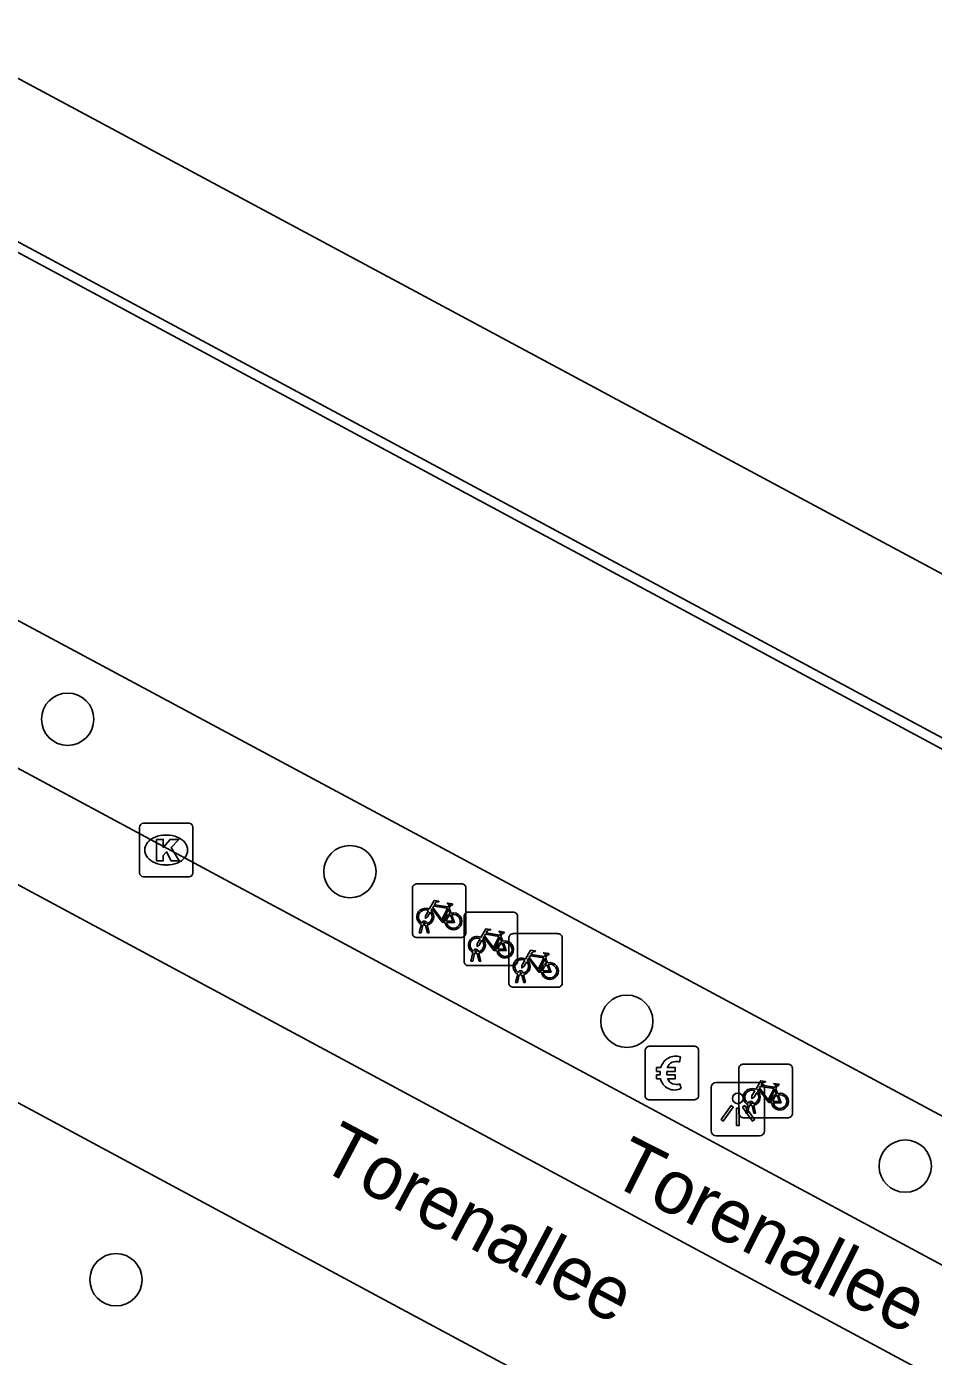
# Model space of a CAD drawing. Extents: x 159489 to 160304, y 383826 to 384530.
# Drawn here: x 159929.09 to 159946.05, y 384136.73 to 384161.6 of the extents above; entities that cross this region are included whole.
import ezdxf

# ---------------------------------------------------------------- set-up
doc = ezdxf.new("R2010")
doc.units = 0
for name, color, linetype in [('IMGEO_Betaalautomaat', 7, 'Continuous'), ('IMGEO_Boom', 7, 'Continuous'), ('IMGEO_Fietsenrek', 7, 'Continuous'), ('IMGEO_Kolk', 7, 'Continuous'), ('IMGEO_Lichtpunt', 7, 'Continuous'), ('IMGEO_Lijnafwatering', 7, 'Continuous'), ('IMGEO_Openbare_ruimte_label', 7, 'Continuous'), ('IMGEO_Pand', 7, 'Continuous'), ('IMGEO_Rijbaan_lokaal_gesloten', 7, 'Continuous'), ('IMGEO_Voetpad_open', 7, 'Continuous')]:
    doc.layers.add(name, color=color, linetype=linetype)

msp = doc.modelspace()

# ---------------------------------------------------------------- linework, layer by layer
at = {"layer": 'IMGEO_Betaalautomaat'}
for p, q in [((159940.662, 384141.609), (159940.662, 384142.45)), ((159940.662, 384142.45), (159940.662, 384141.609)), ((159940.737, 384142.533), (159941.578, 384142.533)), ((159941.578, 384142.533), (159940.737, 384142.533)), ((159941.661, 384142.459), (159941.661, 384141.618)), ((159941.661, 384141.618), (159941.661, 384142.459)), ((159941.324, 384142.338), (159941.307, 384142.238)), ((159940.945, 384141.997), (159940.945, 384142.065)), ((159941.066, 384142.065), (159941.066, 384141.997)), ((159941.311, 384141.832), (159941.333, 384141.745)), ((159941.587, 384141.534), (159940.746, 384141.534)), ((159940.746, 384141.534), (159941.587, 384141.534))]:
    msp.add_line(p, q, dxfattribs=at)
for points in [[(159940.945, 384142.065), (159940.876, 384142.065), (159940.876, 384142.134), (159940.955, 384142.134)], [(159940.95, 384141.928), (159940.876, 384141.928), (159940.876, 384141.997), (159940.945, 384141.997)], [(159941.077, 384142.134), (159941.224, 384142.134), (159941.224, 384142.065), (159941.066, 384142.065)], [(159941.066, 384141.997), (159941.224, 384141.997), (159941.224, 384141.928), (159941.08, 384141.928)]]:
    msp.add_lwpolyline(points, dxfattribs=at)
for centre, radius, start, end in [((159940.74, 384142.456), 0.0779, 92.4484, 184.2845), ((159940.74, 384142.456), 0.0779, 92.4484, 184.2845), ((159941.584, 384142.456), 0.0779, 2.4484, 94.2845), ((159941.584, 384142.456), 0.0779, 2.4484, 94.2845), ((159941.238, 384142.058), 0.293, 73.014, 165.0139), ((159941.244, 384142.071), 0.179, 69.3236, 159.5683), ((159941.211, 384141.983), 0.267, 191.8096, 297.0389), ((159941.244, 384141.998), 0.179, 202.7625, 291.8693), ((159940.74, 384141.612), 0.0779, 182.4484, 274.2845), ((159940.74, 384141.612), 0.0779, 182.4484, 274.2845), ((159941.584, 384141.612), 0.0779, 272.4484, 4.2845), ((159941.584, 384141.612), 0.0779, 272.4484, 4.2845)]:
    msp.add_arc(centre, radius, start, end, dxfattribs=at)
at = {"layer": 'IMGEO_Boom'}
for centre in [(159929.858, 384148.65), (159935.138, 384145.8), (159940.319, 384143.002), (159945.528, 384140.293), (159930.762, 384138.168)]:
    msp.add_circle(centre, 0.489, dxfattribs=at)
at = {"layer": 'IMGEO_Fietsenrek'}
for p, q in [((159936.308, 384144.645), (159936.308, 384145.486)), ((159936.308, 384145.486), (159936.308, 384144.645)), ((159936.383, 384145.57), (159937.224, 384145.57)), ((159937.224, 384145.57), (159936.383, 384145.57)), ((159937.308, 384145.495), (159937.308, 384144.654)), ((159937.308, 384144.654), (159937.308, 384145.495)), ((159936.995, 384145.119), (159937.031, 384145.024)), ((159937.275, 384144.118), (159937.275, 384144.959)), ((159937.275, 384144.959), (159937.275, 384144.118)), ((159937.35, 384145.043), (159938.191, 384145.043)), ((159938.191, 384145.043), (159937.35, 384145.043)), ((159938.275, 384144.968), (159938.275, 384144.127)), ((159938.275, 384144.127), (159938.275, 384144.968)), ((159936.435, 384144.654), (159936.474, 384144.814)), ((159936.469, 384144.654), (159936.435, 384144.654)), ((159936.504, 384144.802), (159936.469, 384144.654)), ((159936.546, 384144.826), (159936.545, 384144.83)), ((159936.587, 384144.654), (159936.553, 384144.796)), ((159936.577, 384144.837), (159936.578, 384144.83)), ((159936.585, 384144.8), (159936.62, 384144.654)), ((159936.62, 384144.654), (159936.587, 384144.654)), ((159938.187, 384144.64), (159939.028, 384144.64)), ((159939.028, 384144.64), (159938.187, 384144.64)), ((159937.233, 384144.57), (159936.392, 384144.57)), ((159936.392, 384144.57), (159937.233, 384144.57)), ((159937.962, 384144.592), (159937.998, 384144.497)), ((159938.112, 384143.715), (159938.112, 384144.556)), ((159938.112, 384144.556), (159938.112, 384143.715)), ((159939.112, 384144.565), (159939.112, 384143.724)), ((159939.112, 384143.724), (159939.112, 384144.565)), ((159937.402, 384144.127), (159937.441, 384144.287)), ((159937.471, 384144.275), (159937.436, 384144.127)), ((159937.513, 384144.299), (159937.512, 384144.303)), ((159937.554, 384144.127), (159937.52, 384144.269)), ((159937.544, 384144.31), (159937.545, 384144.303)), ((159937.552, 384144.273), (159937.587, 384144.127)), ((159938.799, 384144.189), (159938.835, 384144.094)), ((159938.2, 384144.043), (159937.359, 384144.043)), ((159937.359, 384144.043), (159938.2, 384144.043)), ((159937.436, 384144.127), (159937.402, 384144.127)), ((159937.587, 384144.127), (159937.554, 384144.127)), ((159938.35, 384143.896), (159938.349, 384143.9)), ((159938.381, 384143.907), (159938.382, 384143.9)), ((159939.037, 384143.64), (159938.196, 384143.64)), ((159938.196, 384143.64), (159939.037, 384143.64)), ((159938.239, 384143.724), (159938.278, 384143.884)), ((159938.273, 384143.724), (159938.239, 384143.724)), ((159938.308, 384143.872), (159938.273, 384143.724)), ((159938.391, 384143.724), (159938.357, 384143.866)), ((159938.389, 384143.87), (159938.424, 384143.724)), ((159938.424, 384143.724), (159938.391, 384143.724)), ((159942.492, 384142.198), (159943.333, 384142.198)), ((159943.333, 384142.198), (159942.492, 384142.198)), ((159942.417, 384141.273), (159942.417, 384142.114)), ((159942.417, 384142.114), (159942.417, 384141.273)), ((159943.417, 384142.123), (159943.417, 384141.282)), ((159943.417, 384141.282), (159943.417, 384142.123)), ((159943.104, 384141.747), (159943.14, 384141.652)), ((159942.544, 384141.282), (159942.583, 384141.442)), ((159942.613, 384141.43), (159942.578, 384141.282)), ((159942.655, 384141.454), (159942.654, 384141.458)), ((159942.696, 384141.282), (159942.662, 384141.424)), ((159942.686, 384141.465), (159942.687, 384141.458)), ((159942.694, 384141.428), (159942.729, 384141.282)), ((159943.342, 384141.198), (159942.501, 384141.198)), ((159942.501, 384141.198), (159943.342, 384141.198)), ((159942.578, 384141.282), (159942.544, 384141.282)), ((159942.729, 384141.282), (159942.696, 384141.282))]:
    msp.add_line(p, q, dxfattribs=at)
for points in [[(159936.621, 384145.096), (159936.716, 384145.26), (159936.802, 384145.246), (159936.804, 384145.237), (159936.748, 384145.226), (159936.721, 384145.181), (159936.977, 384145.14)], [(159936.964, 384145.115), (159936.707, 384145.156), (159936.69, 384145.127), (159936.857, 384144.907), (159936.964, 384145.115)], [(159936.977, 384145.14), (159937.002, 384145.189), (159936.996, 384145.193), (159936.973, 384145.197), (159936.961, 384145.204), (159936.96, 384145.207), (159936.962, 384145.212), (159937.057, 384145.197), (159937.059, 384145.187), (159937.049, 384145.174), (159937.037, 384145.168), (159937.023, 384145.174), (159936.995, 384145.119)], [(159936.642, 384145.044), (159936.59, 384144.954), (159936.55, 384144.929), (159936.551, 384144.976), (159936.606, 384145.07)], [(159936.917, 384144.852), (159936.867, 384144.852), (159936.676, 384145.103), (159936.657, 384145.071)], [(159937.012, 384145.017), (159936.982, 384145.094), (159936.873, 384144.876), (159936.916, 384144.876)], [(159936.946, 384144.876), (159937.066, 384144.875), (159937.022, 384144.989)], [(159937.042, 384144.996), (159937.097, 384144.851), (159936.947, 384144.851)], [(159937.588, 384144.569), (159937.683, 384144.733), (159937.769, 384144.719), (159937.771, 384144.71), (159937.715, 384144.699), (159937.688, 384144.654), (159937.944, 384144.613)], [(159937.944, 384144.613), (159937.969, 384144.662), (159937.963, 384144.666), (159937.94, 384144.67), (159937.928, 384144.677), (159937.927, 384144.68), (159937.929, 384144.685), (159938.024, 384144.67), (159938.026, 384144.66), (159938.016, 384144.647), (159938.004, 384144.641), (159937.99, 384144.647), (159937.962, 384144.592)], [(159937.609, 384144.517), (159937.557, 384144.427), (159937.517, 384144.402), (159937.518, 384144.449), (159937.573, 384144.543)], [(159937.884, 384144.325), (159937.834, 384144.325), (159937.643, 384144.576), (159937.624, 384144.544)], [(159937.931, 384144.588), (159937.674, 384144.629), (159937.657, 384144.6), (159937.824, 384144.38), (159937.931, 384144.588)], [(159937.979, 384144.49), (159937.949, 384144.567), (159937.84, 384144.349), (159937.883, 384144.349)], [(159937.913, 384144.349), (159938.033, 384144.348), (159937.989, 384144.462)], [(159938.009, 384144.469), (159938.064, 384144.324), (159937.914, 384144.324)], [(159938.446, 384144.114), (159938.394, 384144.024), (159938.354, 384143.999), (159938.355, 384144.046), (159938.41, 384144.14)], [(159938.425, 384144.166), (159938.52, 384144.33), (159938.606, 384144.316), (159938.608, 384144.307), (159938.552, 384144.296), (159938.525, 384144.251), (159938.781, 384144.21)], [(159938.721, 384143.922), (159938.671, 384143.922), (159938.48, 384144.173), (159938.461, 384144.141)], [(159938.768, 384144.185), (159938.511, 384144.226), (159938.494, 384144.197), (159938.661, 384143.977), (159938.768, 384144.185)], [(159938.816, 384144.087), (159938.786, 384144.164), (159938.677, 384143.946), (159938.72, 384143.946)], [(159938.781, 384144.21), (159938.806, 384144.259), (159938.8, 384144.263), (159938.777, 384144.267), (159938.765, 384144.274), (159938.764, 384144.277), (159938.766, 384144.282), (159938.861, 384144.267), (159938.863, 384144.257), (159938.853, 384144.244), (159938.841, 384144.238), (159938.827, 384144.244), (159938.799, 384144.189)], [(159938.75, 384143.946), (159938.87, 384143.945), (159938.826, 384144.059)], [(159938.846, 384144.066), (159938.901, 384143.921), (159938.751, 384143.921)], [(159942.751, 384141.672), (159942.699, 384141.582), (159942.659, 384141.557), (159942.66, 384141.604), (159942.715, 384141.698)], [(159942.73, 384141.724), (159942.825, 384141.888), (159942.911, 384141.874), (159942.913, 384141.865), (159942.857, 384141.854), (159942.83, 384141.809), (159943.086, 384141.768)], [(159943.026, 384141.48), (159942.976, 384141.48), (159942.785, 384141.731), (159942.766, 384141.699)], [(159943.073, 384141.743), (159942.816, 384141.784), (159942.799, 384141.755), (159942.966, 384141.535), (159943.073, 384141.743)], [(159943.121, 384141.645), (159943.091, 384141.722), (159942.982, 384141.504), (159943.025, 384141.504)], [(159943.086, 384141.768), (159943.111, 384141.817), (159943.105, 384141.821), (159943.082, 384141.825), (159943.07, 384141.832), (159943.069, 384141.835), (159943.071, 384141.84), (159943.166, 384141.825), (159943.168, 384141.815), (159943.158, 384141.802), (159943.146, 384141.796), (159943.132, 384141.802), (159943.104, 384141.747)], [(159943.055, 384141.504), (159943.175, 384141.503), (159943.131, 384141.617)], [(159943.151, 384141.624), (159943.206, 384141.479), (159943.056, 384141.479)]]:
    msp.add_lwpolyline(points, dxfattribs=at)
for centre, radius, start, end in [((159936.386, 384145.492), 0.0779, 92.4484, 184.2845), ((159936.386, 384145.492), 0.0779, 92.4484, 184.2845), ((159937.23, 384145.492), 0.0779, 2.4484, 94.2845), ((159937.23, 384145.492), 0.0779, 2.4484, 94.2845), ((159936.548, 384144.955), 0.159, 62.6766, 242.1369), ((159936.548, 384144.955), 0.129, 63.3192, 238.903), ((159936.548, 384144.955), 0.129, 283.6043, 43.4302), ((159936.548, 384144.955), 0.159, 283.5766, 46.6042), ((159937.075, 384144.871), 0.159, 113.3408, 178.3217), ((159937.075, 384144.871), 0.159, 187.0065, 105.7708), ((159937.075, 384144.871), 0.129, 113.923, 177.9556), ((159937.075, 384144.871), 0.129, 188.6715, 104.5883), ((159937.353, 384144.965), 0.0779, 92.4484, 184.2845), ((159937.353, 384144.965), 0.0779, 92.4484, 184.2845), ((159938.197, 384144.965), 0.0779, 2.4484, 94.2845), ((159938.197, 384144.965), 0.0779, 2.4484, 94.2845), ((159936.386, 384144.648), 0.0779, 182.4484, 274.2845), ((159936.386, 384144.648), 0.0779, 182.4484, 274.2845), ((159936.528, 384144.826), 0.0499, 12.8025, 158.6934), ((159936.548, 384144.955), 0.159, 253.9967, 271.7867), ((159936.528, 384144.826), 0.0174, 12.8025, 163.4502), ((159936.548, 384144.955), 0.129, 253.415, 269.0204), ((159937.23, 384144.648), 0.0779, 272.4484, 4.2845), ((159937.23, 384144.648), 0.0779, 272.4484, 4.2845), ((159938.19, 384144.562), 0.0779, 92.4484, 184.2845), ((159938.19, 384144.562), 0.0779, 92.4484, 184.2845), ((159939.034, 384144.562), 0.0779, 2.4484, 94.2845), ((159939.034, 384144.562), 0.0779, 2.4484, 94.2845), ((159937.515, 384144.428), 0.159, 62.6766, 242.1369), ((159937.515, 384144.428), 0.129, 63.3192, 238.903), ((159937.515, 384144.428), 0.129, 283.6043, 43.4302), ((159937.515, 384144.428), 0.159, 283.5766, 46.6042), ((159938.042, 384144.344), 0.159, 113.3408, 178.3217), ((159938.042, 384144.344), 0.159, 187.0065, 105.7708), ((159938.042, 384144.344), 0.129, 113.923, 177.9556), ((159938.042, 384144.344), 0.129, 188.6715, 104.5883), ((159937.495, 384144.299), 0.0499, 12.8025, 158.6934), ((159937.515, 384144.428), 0.159, 253.9967, 271.7867), ((159937.495, 384144.299), 0.0174, 12.8025, 163.4502), ((159937.515, 384144.428), 0.129, 253.415, 269.0204), ((159938.352, 384144.025), 0.159, 62.6766, 242.1369), ((159938.352, 384144.025), 0.129, 63.3192, 238.903), ((159938.352, 384144.025), 0.159, 283.5766, 46.6042), ((159937.353, 384144.121), 0.0779, 182.4484, 274.2845), ((159937.353, 384144.121), 0.0779, 182.4484, 274.2845), ((159938.197, 384144.121), 0.0779, 272.4484, 4.2845), ((159938.197, 384144.121), 0.0779, 272.4484, 4.2845), ((159938.332, 384143.896), 0.0499, 12.8025, 158.6934), ((159938.332, 384143.896), 0.0174, 12.8025, 163.4502), ((159938.352, 384144.025), 0.129, 253.415, 269.0204), ((159938.352, 384144.025), 0.129, 283.6043, 43.4302), ((159938.879, 384143.941), 0.159, 113.3408, 178.3217), ((159938.879, 384143.941), 0.159, 187.0065, 105.7708), ((159938.879, 384143.941), 0.129, 113.923, 177.9556), ((159938.879, 384143.941), 0.129, 188.6715, 104.5883), ((159938.19, 384143.718), 0.0779, 182.4484, 274.2845), ((159938.19, 384143.718), 0.0779, 182.4484, 274.2845), ((159938.352, 384144.025), 0.159, 253.9967, 271.7867), ((159939.034, 384143.718), 0.0779, 272.4484, 4.2845), ((159939.034, 384143.718), 0.0779, 272.4484, 4.2845), ((159942.495, 384142.12), 0.0779, 92.4484, 184.2845), ((159942.495, 384142.12), 0.0779, 92.4484, 184.2845), ((159943.339, 384142.12), 0.0779, 2.4484, 94.2845), ((159943.339, 384142.12), 0.0779, 2.4484, 94.2845), ((159942.657, 384141.583), 0.159, 62.6766, 242.1369), ((159942.657, 384141.583), 0.129, 63.3192, 238.903), ((159942.657, 384141.583), 0.129, 283.6043, 43.4302), ((159942.657, 384141.583), 0.159, 283.5766, 46.6042), ((159943.184, 384141.499), 0.159, 187.0065, 105.7708), ((159942.637, 384141.454), 0.0499, 12.8025, 158.6934), ((159942.657, 384141.583), 0.159, 253.9967, 271.7867), ((159942.637, 384141.454), 0.0174, 12.8025, 163.4502), ((159942.657, 384141.583), 0.129, 253.415, 269.0204), ((159943.184, 384141.499), 0.159, 113.3408, 178.3217), ((159943.184, 384141.499), 0.129, 113.923, 177.9556), ((159943.184, 384141.499), 0.129, 188.6715, 104.5883), ((159942.495, 384141.276), 0.0779, 182.4484, 274.2845), ((159942.495, 384141.276), 0.0779, 182.4484, 274.2845), ((159943.339, 384141.276), 0.0779, 272.4484, 4.2845), ((159943.339, 384141.276), 0.0779, 272.4484, 4.2845)]:
    msp.add_arc(centre, radius, start, end, dxfattribs=at)
at = {"layer": 'IMGEO_Kolk'}
for p, q in [((159931.201, 384145.778), (159931.201, 384146.63)), ((159931.276, 384146.704), (159932.128, 384146.704)), ((159932.202, 384146.63), (159932.202, 384145.778)), ((159931.689, 384146.484), (159931.714, 384146.484)), ((159931.712, 384145.924), (159931.687, 384145.924)), ((159932.128, 384145.704), (159931.276, 384145.704))]:
    msp.add_line(p, q, dxfattribs=at)
for points in [[(159931.201, 384145.778), (159931.201, 384146.63)], [(159931.276, 384146.704), (159932.128, 384146.704)], [(159932.202, 384146.63), (159932.202, 384145.778)], [(159931.522, 384146.404), (159931.645, 384146.404), (159931.645, 384146.253), (159931.775, 384146.404), (159931.939, 384146.404), (159931.793, 384146.253), (159931.946, 384146.004), (159931.794, 384146.004), (159931.709, 384146.168), (159931.645, 384146.101), (159931.645, 384146.004), (159931.522, 384146.004), (159931.522, 384146.404)], [(159932.128, 384145.704), (159931.276, 384145.704)]]:
    msp.add_lwpolyline(points, dxfattribs=at)
for centre, start, end in [((159931.278, 384146.628), 91.552, 178.448), ((159931.278, 384146.628), 91.552, 178.448), ((159932.126, 384146.628), 1.552, 88.448), ((159932.126, 384146.628), 1.552, 88.448), ((159931.278, 384145.78), 181.552, 268.448), ((159931.278, 384145.78), 181.552, 268.448), ((159932.126, 384145.78), 271.552, 358.448), ((159932.126, 384145.78), 271.552, 358.448)]:
    msp.add_arc(centre, 0.0765, start, end, dxfattribs=at)
for centre, major_axis, ratio, start_param, end_param in [((159931.688, 384146.204), (-0.387, 0.002), 0.722429, 4.712389, 7.853982), ((159931.713, 384146.204), (-0.39, 0.002), 0.717154, 1.570796, 4.712389)]:
    msp.add_ellipse(centre, major_axis=major_axis, ratio=ratio, start_param=start_param, end_param=end_param, dxfattribs=at)
at = {"layer": 'IMGEO_Lichtpunt'}
for p, q in [((159941.898, 384141.761), (159941.898, 384140.954)), ((159941.898, 384141.761), (159941.898, 384140.954)), ((159942.8, 384141.856), (159941.992, 384141.856)), ((159942.8, 384141.856), (159941.992, 384141.856)), ((159942.894, 384140.954), (159942.894, 384141.761)), ((159942.894, 384140.954), (159942.894, 384141.761)), ((159941.992, 384140.86), (159942.8, 384140.86)), ((159941.992, 384140.86), (159942.8, 384140.86))]:
    msp.add_line(p, q, dxfattribs=at)
for points in [[(159942.272, 384141.425), (159942.311, 384141.397), (159942.123, 384141.135), (159942.085, 384141.162), (159942.272, 384141.425)], [(159942.484, 384141.397), (159942.522, 384141.424), (159942.709, 384141.162), (159942.67, 384141.134), (159942.484, 384141.397)], [(159942.374, 384141.377), (159942.421, 384141.377), (159942.421, 384141.055), (159942.374, 384141.055), (159942.374, 384141.377)]]:
    msp.add_lwpolyline(points, dxfattribs=at)
msp.add_circle((159942.397, 384141.559), 0.0994, dxfattribs=at)
for centre, start, end in [((159941.992, 384141.761), 90, 180), ((159941.992, 384141.761), 90, 180), ((159942.8, 384141.761), 0, 90), ((159942.8, 384141.761), 0, 90), ((159941.992, 384140.954), 180, 270), ((159941.992, 384140.954), 180, 270), ((159942.8, 384140.954), 270, 0), ((159942.8, 384140.954), 270, 360)]:
    msp.add_arc(centre, 0.0946, start, end, dxfattribs=at)
at = {"layer": 'IMGEO_Lijnafwatering'}
for points in [[(159917.499, 384163.714), (159934.155, 384154.775)], [(159934.155, 384154.775), (159950.81, 384145.837)]]:
    msp.add_lwpolyline(points, dxfattribs=at)
at = {"layer": 'IMGEO_Pand'}
msp.add_lwpolyline([(160002.485, 384121.2), (159993.803, 384125.855), (159988.602, 384128.644), (159972.877, 384137.075), (159970.476, 384138.363), (159951.365, 384148.61), (159948.39, 384150.205), (159940.225, 384154.583), (159935.251, 384157.25), (159918.126, 384166.432), (159912.035, 384169.676), (159906.775, 384172.478), (159901.96, 384175.043), (159901.938, 384175.054)], dxfattribs=at)
at = {"layer": 'IMGEO_Rijbaan_lokaal_gesloten'}
for points in [[(159998.32, 384113.209), (159991.549, 384116.926), (159897.742, 384167.217), (159900.602, 384172.559), (159905.438, 384169.984), (159910.698, 384167.182), (160001.178, 384118.557)], [(159970.012, 384125.655), (159969.104, 384123.965), (159911.095, 384155.132), (159912.004, 384156.822)], [(159939.687, 384135.699), (159936.03, 384137.66), (159905.423, 384154.113), (159901.046, 384156.469)]]:
    msp.add_lwpolyline(points, dxfattribs=at)
at = {"layer": 'IMGEO_Voetpad_open'}
msp.add_lwpolyline([(159912.004, 384156.822), (159970.012, 384125.655)], dxfattribs=at)

# ---------------------------------------------------------------- texts
at = {"layer": 'IMGEO_Openbare_ruimte_label'}
for rotation, p in [(332.1027, (159934.517, 384140.275)), (333.2044, (159939.962, 384139.983))]:
    msp.add_text('Torenallee', height=1, rotation=rotation, dxfattribs=at).set_placement(p)

doc.saveas('drawing.dxf')
